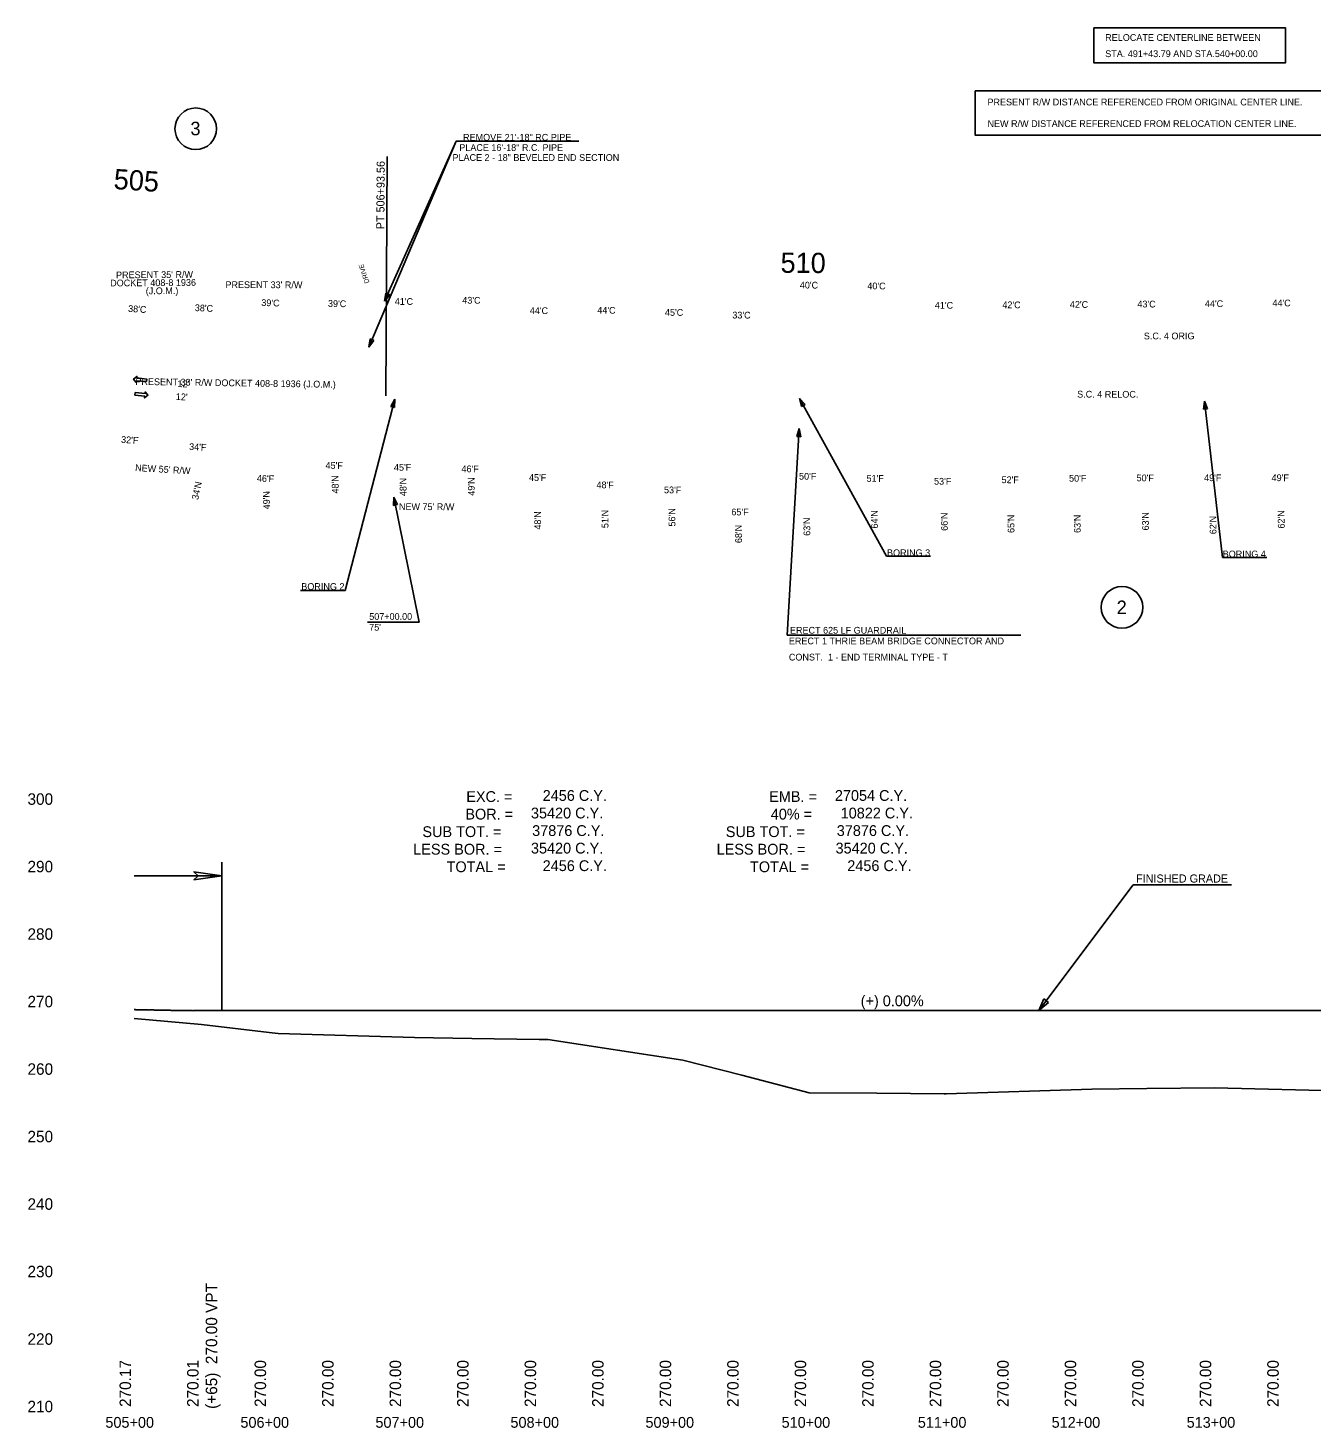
# Model space of a CAD drawing. Extents: x 49105 to 50775, y 45514 to 53458.
# Drawn here: x 49109 to 50060, y 47814 to 48851 of the extents above; entities that cross this region are included whole.
import ezdxf

# ---------------------------------------------------------------- set-up
doc = ezdxf.new("R2010")
doc.units = 0
for name, color, linetype in [('Level 1', 7, 'Continuous'), ('Level 12', 7, 'Continuous'), ('Level 14', 7, 'Continuous'), ('Level 19', 7, 'Continuous'), ('Level 20', 7, 'Continuous'), ('Level 21', 7, 'Continuous'), ('Level 24', 7, 'Continuous'), ('Level 27', 7, 'Continuous'), ('Level 29', 7, 'Continuous'), ('Level 33', 7, 'Continuous'), ('Level 39', 7, 'Continuous'), ('Level 40', 7, 'Continuous'), ('Level 41', 7, 'Continuous'), ('Level 42', 7, 'Continuous'), ('Level 43', 7, 'Continuous'), ('Level 45', 7, 'Continuous'), ('Level 48', 7, 'Continuous'), ('Level 6', 7, 'Continuous'), ('Level 8', 7, 'Continuous')]:
    doc.layers.add(name, color=color, linetype=linetype)

msp = doc.modelspace()

# ---------------------------------------------------------------- linework, layer by layer
at = {"layer": 'Level 1'}
for p, q in [((49380.9, 48575.9), (49344.2, 48434.1)), ((49344.2, 48434.1), (49311.2, 48434.1)), ((49927.8, 48216.1), (49858, 48123.1)), ((49927.8, 48216.1), (50000.6, 48216.1))]:
    msp.add_line(p, q, dxfattribs=at)
msp.add_lwpolyline([(49252.9, 48222.9), (49232.1, 48225.8), (49235.3, 48222.9), (49232.1, 48219.9)], close=True, dxfattribs=at)
at = {"layer": 'Level 12'}
for centre in [(49233.5, 48776.2), (49919.5, 48421.7)]:
    msp.add_circle(centre, 15.4, dxfattribs=at)
at = {"layer": 'Level 14'}
for points in [[(49197, 48588.9), (49197.2, 48590.8), (49189.9, 48591.6), (49190, 48592.8), (49187.5, 48590.8), (49189.5, 48588.3), (49189.7, 48589.6)], [(49188.7, 48580.8), (49188.5, 48578.9), (49195.8, 48578.1), (49195.6, 48576.8), (49198.1, 48578.8), (49196.1, 48581.3), (49196, 48580)]]:
    msp.add_lwpolyline(points, close=True, dxfattribs=at)
at = {"layer": 'Level 19'}
msp.add_line((49374.2, 48578.4), (49375.4, 48755.6), dxfattribs=at)
at = {"layer": 'Level 24'}
for p, q in [((49374.4, 48654.5), (49373.4, 48648.4)), ((49373.4, 48648.4), (49377.2, 48653.3)), ((49377.2, 48653.3), (49374.4, 48654.5)), ((49362.6, 48620.5), (49361.6, 48614.4)), ((49365.4, 48619.4), (49362.6, 48620.5)), ((49361.6, 48614.4), (49365.4, 48619.4)), ((49380.9, 48575.9), (49377.9, 48570.4)), ((49377.9, 48570.4), (49380.8, 48569.7)), ((49380.8, 48569.7), (49380.9, 48575.9)), ((49680.7, 48576.4), (49682.2, 48570.5)), ((49684.9, 48571.9), (49680.7, 48576.4)), ((49682.2, 48570.5), (49684.9, 48571.9)), ((49980.7, 48574.5), (49979.9, 48568.4)), ((49979.9, 48568.4), (49982.8, 48568.7)), ((49982.8, 48568.7), (49980.7, 48574.5)), ((49680.5, 48554.2), (49678.7, 48548.3)), ((49678.7, 48548.3), (49681.7, 48548.1)), ((49681.7, 48548.1), (49680.5, 48554.2)), ((49380.2, 48503.4), (49379.9, 48497.2)), ((49379.9, 48497.2), (49382.9, 48497.8)), ((49382.9, 48497.8), (49380.2, 48503.4)), ((49861.6, 48131.6), (49858, 48123.1)), ((49858, 48123.1), (49865.2, 48128.9)), ((49865.2, 48128.9), (49861.6, 48131.6))]:
    msp.add_line(p, q, dxfattribs=at)
at = {"layer": 'Level 27'}
for p, q in [((49680.5, 48554.2), (49671.6, 48401.1)), ((49671.6, 48401.1), (49844.7, 48401.1))]:
    msp.add_line(p, q, dxfattribs=at)
at = {"layer": 'Level 29'}
for p, q in [((49680.7, 48576.4), (49745.2, 48459.5)), ((49980.7, 48574.5), (49994, 48458.6)), ((49745.2, 48459.5), (49777.7, 48459.5)), ((49994, 48458.6), (50026.7, 48458.6))]:
    msp.add_line(p, q, dxfattribs=at)
at = {"layer": 'Level 33'}
for p, q in [((49380.2, 48503.4), (49399.1, 48410.6)), ((49399.1, 48410.6), (49360.6, 48410.6))]:
    msp.add_line(p, q, dxfattribs=at)
at = {"layer": 'Level 40'}
msp.add_lwpolyline([(49187.9, 48117.1), (49237.9, 48112.6), (49287.9, 48106.7), (49294.5, 48105.9), (49395.5, 48102.9), (49437.9, 48102.2), (49487.9, 48101.6), (49494.3, 48101.6), (49594.2, 48086.2), (49637.9, 48075), (49687.9, 48062.1), (49737.9, 48061.9), (49787.9, 48061.3), (49789.2, 48061.3), (49897.1, 48064.8), (49937.9, 48065.3), (49987.9, 48065.8), (50037.9, 48064.4), (50087.9, 48063.3)], dxfattribs=at)
at = {"layer": 'Level 41'}
for p, q in [((49252.9, 48232.9), (49252.9, 48122.9)), ((49187.9, 48222.9), (49252.9, 48222.9))]:
    msp.add_line(p, q, dxfattribs=at)
at = {"layer": 'Level 45'}
msp.add_line((49252.9, 48122.9), (50399.9, 48122.9), dxfattribs=at)
msp.add_spline([(49187.9, 48123.7), (49189.2, 48123.6), (49190.5, 48123.6), (49191.8, 48123.6), (49193.1, 48123.6), (49194.4, 48123.5), (49195.7, 48123.5), (49197, 48123.5), (49198.3, 48123.4), (49199.6, 48123.4), (49200.9, 48123.4), (49202.2, 48123.4), (49203.5, 48123.3), (49204.8, 48123.3), (49206.1, 48123.3), (49207.4, 48123.3), (49208.7, 48123.2), (49210, 48123.2), (49211.3, 48123.2), (49212.6, 48123.2), (49213.9, 48123.2), (49215.2, 48123.1), (49216.5, 48123.1), (49217.8, 48123.1), (49219.1, 48123.1), (49220.4, 48123.1), (49221.7, 48123), (49223, 48123), (49224.3, 48123), (49225.6, 48123), (49226.9, 48123), (49228.2, 48123), (49229.5, 48123), (49230.8, 48122.9), (49232.1, 48122.9), (49233.4, 48122.9), (49234.7, 48122.9), (49236, 48122.9), (49237.3, 48122.9), (49238.6, 48122.9), (49239.9, 48122.9), (49241.2, 48122.9), (49242.5, 48122.9), (49243.8, 48122.9), (49245.1, 48122.9), (49246.4, 48122.9), (49247.7, 48122.9), (49249, 48122.9), (49250.3, 48122.9), (49251.6, 48122.9), (49252.9, 48122.9)], degree=3, dxfattribs=at)
at = {"layer": 'Level 6'}
for p in [(49361.6, 48614.4), (49373.4, 48648.4), (49517.2, 48766.9)]:
    msp.add_line(p, (49426.3, 48766.9), dxfattribs=at)
for points in [[(49898.6, 48850.9), (50040.7, 48850.9), (50040.7, 48825.1), (49898.6, 48825.1)], [(49810.7, 48804.4), (50079.9, 48804.4), (50079.9, 48771.5), (49810.7, 48771.5)]]:
    msp.add_lwpolyline(points, close=True, dxfattribs=at)

# ---------------------------------------------------------------- texts
at = {"layer": 'Level 1'}
for s, rotation, p in [(' DOCKET 408-8 1936 ', 0.4075, (49168.3, 48659.4)), ("PRESENT 35' R/W", 0.4075, (49174.5, 48665.4)), ("PRESENT 33' R/W ", 359.8723, (49255.5, 48658.2)), ('(J.O.M.)', 0.4075, (49196.5, 48653.6)), ("PRESENT 33' R/W DOCKET 408-8 1936 (J.O.M.)", 359.1607, (49188.8, 48586.5))]:
    msp.add_text(s, height=5, rotation=rotation, dxfattribs=at).set_placement(p)
for s, height, p in [('BORING 3', 5, (49745.5, 48459.6)), ('BORING 4', 5, (49994.1, 48458.7)), ('BORING 2', 5, (49311.7, 48434.6)), ('EXC. =', 8, (49433.9, 48277.5)), (' 2456 C.Y.', 8, (49487.5, 48278.3)), ('EMB. =', 8, (49658.2, 48277.5)), (' 27054 C.Y.', 8, (49703.9, 48278.3)), ('BOR. =', 8, (49433.2, 48264.5)), (' 35420 C.Y.', 8, (49478.8, 48265.3)), ('40% =', 8, (49659.4, 48264.5)), (' 10822 C.Y.', 8, (49708.2, 48265.3)), ('SUB TOT. =', 8, (49401.4, 48251.5)), (' 37876 C.Y.', 8, (49479.7, 48252.3)), ('SUB TOT. =', 8, (49626.1, 48251.5)), (' 37876 C.Y.', 8, (49705.3, 48252.3)), (' 35420 C.Y.', 8, (49478.8, 48239.3)), (' 35420 C.Y.', 8, (49704.4, 48239.3)), ('LESS BOR. =', 8, (49394.6, 48238.5)), ('LESS BOR. =', 8, (49619.3, 48238.5)), ('TOTAL =', 8, (49419.3, 48225.5)), (' 2456 C.Y.', 8, (49487.5, 48226.3)), ('TOTAL =', 8, (49644, 48225.5)), (' 2456 C.Y.', 8, (49713.1, 48226.3)), ('FINISHED GRADE', 6, (49929.9, 48217.8))]:
    msp.add_text(s, height=height, dxfattribs=at).set_placement(p)
at = {"layer": 'Level 12'}
for s, p in [('3', (49229.6, 48771.4)), ('2', (49915.6, 48416.7))]:
    msp.add_text(s, height=10, dxfattribs=at).set_placement(p)
at = {"layer": 'Level 19'}
for s, height, rotation, p in [('505', 15, 356.2461, (49172.4, 48731.6)), ('PT 506+93.56', 6, 89.6334, (49373.2, 48701.7)), ('510', 15, 359.6334, (49666.6, 48669.5))]:
    msp.add_text(s, height=height, rotation=rotation, dxfattribs=at).set_placement(p)
at = {"layer": 'Level 20'}
for p in [(49219.9, 48584.9), (49218.7, 48575.3)]:
    msp.add_text("12'", height=5, rotation=357.8501, dxfattribs=at).set_placement(p)
at = {"layer": 'Level 21'}
msp.add_text('S.C. 4 ORIG', height=5, rotation=0.0467, dxfattribs=at).set_placement((49935.7, 48620.2))
at = {"layer": 'Level 27'}
for s, p in [('ERECT 625 LF GUARDRAIL', (49673.6, 48402.2)), ('ERECT 1 THRIE BEAM BRIDGE CONNECTOR AND ', (49672.8, 48394.3)), ('CONST.  1 - END TERMINAL TYPE - T', (49672.8, 48382.3))]:
    msp.add_text(s, height=5, dxfattribs=at).set_placement(p)
at = {"layer": 'Level 29'}
for s, p in [(' PLACE 2 - 18" BEVELED END SECTION', (49421.8, 48752.4)), ('PLACE 16\'-18" R.C. PIPE', (49428.7, 48759.8))]:
    msp.add_text(s, height=5, dxfattribs=at).set_placement(p)
at = {"layer": 'Level 33'}
for s, rotation, p in [("NEW 55' R/W", 356.5816, (49188.5, 48522.7)), ("NEW 75' R/W", 359.7811, (49384, 48493.8))]:
    msp.add_text(s, height=5, rotation=rotation, dxfattribs=at).set_placement(p)
for s, p in [('507+00.00', (49362, 48412.4)), ("75'", (49362, 48404.4))]:
    msp.add_text(s, height=5, dxfattribs=at).set_placement(p)
at = {"layer": 'Level 39'}
msp.add_text('S.C. 4 RELOC.', height=5, rotation=359.8564, dxfattribs=at).set_placement((49886.3, 48577.1))
at = {"layer": 'Level 41'}
msp.add_text('(+) 0.00%', height=8, dxfattribs=at).set_placement((49726, 48126.2))
msp.add_text('(+65)  270.00 VPT', height=8.5, rotation=90, dxfattribs=at).set_placement((49249.4, 47827.9))
at = {"layer": 'Level 42'}
for s, height, p in [('300', 8.5, (49108.9, 48275.4)), ('290', 8.5, (49108.9, 48225.4)), ('280', 8.5, (49108.9, 48175.4)), ('270', 8.5, (49108.9, 48125.4)), ('260', 8.5, (49108.9, 48075.4)), ('250', 8.5, (49108.9, 48025.4)), ('240', 8.5, (49108.9, 47975.4)), ('230', 8.5, (49108.9, 47925.4)), ('220', 8.5, (49108.9, 47875.4)), ('210', 8.5, (49108.9, 47825.4)), ('505+00', 8, (49166.6, 47813.9)), ('506+00', 8, (49266.6, 47813.9)), ('507+00', 8, (49366.6, 47813.9)), ('508+00', 8, (49466.6, 47813.9)), ('509+00', 8, (49566.6, 47813.9)), ('510+00', 8, (49667.4, 47813.9)), ('511+00', 8, (49768.3, 47813.9)), ('512+00', 8, (49867.4, 47813.9)), ('513+00', 8, (49967.4, 47813.9))]:
    msp.add_text(s, height=height, dxfattribs=at).set_placement(p)
at = {"layer": 'Level 43'}
for s, p in [('270.17', (49185.6, 47829.3)), ('270.01', (49235.6, 47829.3)), ('270.00', (49285.6, 47829.3)), ('270.00', (49335.6, 47829.3)), ('270.00', (49385.6, 47829.3)), ('270.00', (49435.6, 47829.3)), ('270.00', (49485.6, 47829.3)), ('270.00', (49535.6, 47829.3)), ('270.00', (49585.6, 47829.3)), ('270.00', (49635.6, 47829.3)), ('270.00', (49685.6, 47829.3)), ('270.00', (49735.6, 47829.3)), ('270.00', (49785.6, 47829.3)), ('270.00', (49835.6, 47829.3)), ('270.00', (49885.6, 47829.3)), ('270.00', (49935.6, 47829.3)), ('270.00', (49985.6, 47829.3)), ('270.00', (50035.6, 47829.3))]:
    msp.add_text(s, height=8.5, rotation=90, dxfattribs=at).set_placement(p)
at = {"layer": 'Level 48'}
for s, rotation, p in [("40'C", 359.6334, (49680.9, 48657.9)), ("40'C", 359.6334, (49730.9, 48657.3)), ("43'C", 359.6334, (49430.9, 48646.7)), ("38'C", 356.2461, (49183.3, 48640.6)), ("38'C", 357.1211, (49232.7, 48641.2)), ("39'C", 357.9961, (49282, 48645)), ("39'C", 358.8711, (49331.4, 48644.3)), ("41'C", 359.6334, (49380.9, 48645.8)), ("44'C", 359.6334, (49480.9, 48639)), ("44'C", 359.6334, (49530.9, 48639.3)), ("45'C", 359.6334, (49581, 48637.7)), ("41'C", 359.6334, (49780.9, 48643)), ("42'C", 359.6334, (49830.9, 48643.3)), ("42'C", 359.6334, (49880.9, 48643.6)), ("43'C", 359.6334, (49930.9, 48643.9)), ("44'C", 359.6334, (49980.9, 48644.2)), ("44'C", 359.6334, (50030.9, 48644.7)), ("33'C", 359.6334, (49630.9, 48635.7)), ("32'F", 356.2461, (49178.1, 48543.6)), ("34'F", 357.1211, (49228.5, 48538.3)), ("45'F", 358.8711, (49329.6, 48524.4)), ("45'F", 359.6334, (49380.3, 48522.9)), ("46'F", 359.6334, (49430.3, 48521.8)), ("46'F", 357.9961, (49278.7, 48514.8)), ("48'N", 90.8528, (49339.4, 48506)), ("48'N", 90.8528, (49389.7, 48504.1)), ("49'N", 90.8528, (49440.2, 48504.4)), ("45'F", 359.6333, (49480.3, 48515.4)), ("50'F", 359.6334, (49680.3, 48516.3)), ("51'F", 359.6334, (49730.3, 48514.7)), ("53'F", 359.6333, (49780.3, 48512.6)), ("52'F", 359.6334, (49830.3, 48513.7)), ("50'F", 359.6334, (49880.3, 48514.8)), ("50'F", 359.6333, (49930.3, 48515.1)), ("49'F", 359.6334, (49980.3, 48515.2)), ("49'F", 359.6334, (50030.3, 48515.2)), ("34'N", 77.917, (49235.3, 48501)), ("49'N", 90.8528, (49288.5, 48494.3)), ("48'F", 359.6334, (49530.3, 48509.9)), ("53'F", 359.6334, (49580.3, 48506.2)), ("48'N", 90.8528, (49489.3, 48479.3)), ("51'N", 90.8528, (49539.2, 48480.4)), ("56'N", 90.8528, (49588.8, 48481.6)), ("65'F", 359.6334, (49630.2, 48489.8)), ("63'N", 90.8528, (49688.7, 48474.7)), ("64'N", 90.8528, (49738.8, 48480.1)), ("66'N", 90.8528, (49790.5, 48478.4)), ("65'N", 90.8528, (49839.9, 48476.8)), ("63'N", 90.8528, (49889, 48476.8)), ("63'N", 90.8528, (49939.5, 48478.7)), ("62'N", 90.8528, (49989.5, 48475.9)), ("62'N", 90.8528, (50040, 48480.1)), ("68'N", 90.8528, (49638.1, 48469.3))]:
    msp.add_text(s, height=5, rotation=rotation, dxfattribs=at).set_placement(p)
at = {"layer": 'Level 6'}
for s, p in [('RELOCATE CENTERLINE BETWEEN', (49907.1, 48841.3)), ('STA. 491+43.79 AND STA.540+00.00', (49907.1, 48829.3)), ('PRESENT R/W DISTANCE REFERENCED FROM ORIGINAL CENTER LINE.', (49819.9, 48793.5)), ('NEW R/W DISTANCE REFERENCED FROM RELOCATION CENTER LINE.', (49819.9, 48777.5)), ('REMOVE 21\'-18" RC PIPE', (49431.5, 48767.4))]:
    msp.add_text(s, height=5, dxfattribs=at).set_placement(p)
at = {"layer": 'Level 8'}
msp.add_text('DRIVE', height=3.5, rotation=108.8976, dxfattribs=at).set_placement((49362.2, 48662.4))

doc.saveas('drawing.dxf')
